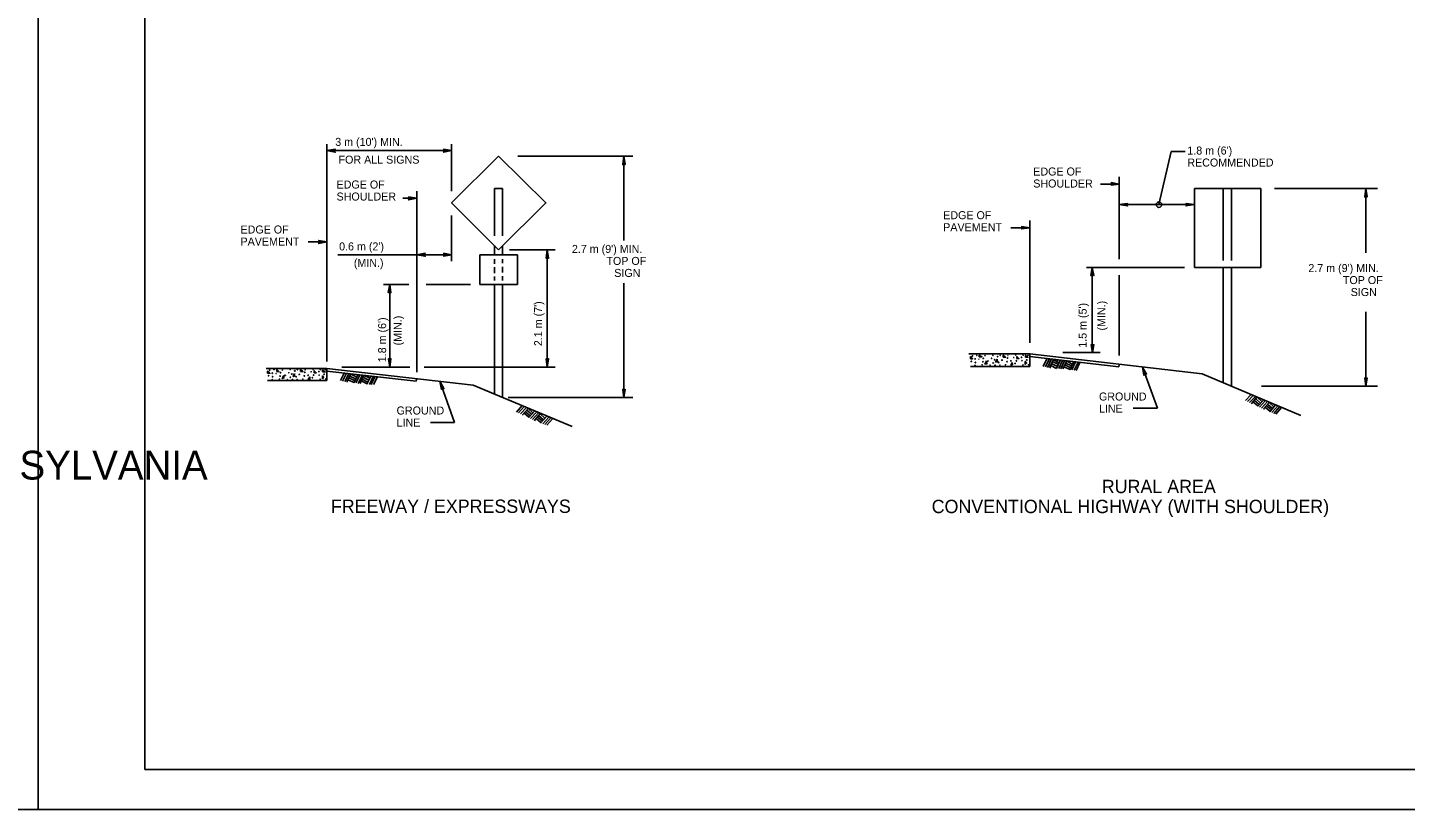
# Model space of a CAD drawing. Extents: x 644358 to 648627, y 294594 to 295782.
# Drawn here: x 646877 to 647394, y 294594 to 294887 of the extents above; entities that cross this region are included whole.
import ezdxf

# ---------------------------------------------------------------- set-up
doc = ezdxf.new("R2010")
doc.units = 0
for name, color, linetype in [('1', 7, 'Continuous'), ('2', 7, 'Continuous'), ('4', 7, 'Continuous'), ('PLT-BNDY', 7, 'Continuous')]:
    doc.layers.add(name, color=color, linetype=linetype)

msp = doc.modelspace()

# ---------------------------------------------------------------- linework, layer by layer
at = {"layer": '1'}
for p, q in [((646921.31, 295172.63), (646921.31, 294608.63)), ((647259.44, 294762.63), (647258.06, 294759.75)), ((647260.31, 294762.5), (647258.94, 294759.63)), ((647261.06, 294762.38), (647259.69, 294759.38)), ((647261.94, 294762.25), (647260.44, 294759.38)), ((647263.06, 294759), (647260.94, 294760.13)), ((647263.44, 294759.75), (647261.19, 294760.88)), ((647263.81, 294760.5), (647261.56, 294761.63)), ((647264.06, 294761.13), (647261.94, 294762.25)), ((647264.44, 294762), (647263.06, 294759)), ((647263.69, 294762), (647263.31, 294762.13)), ((647265.31, 294762), (647263.94, 294759)), ((647266.06, 294761.88), (647264.69, 294758.88)), ((647266.94, 294761.75), (647265.44, 294758.88)), ((647268.44, 294759.25), (647266.19, 294760.38)), ((647268.69, 294760), (647266.56, 294761)), ((647269.06, 294760.63), (647266.94, 294761.75)), ((647267.81, 294761.63), (647267.44, 294761.75)), ((647269.44, 294761.5), (647268.06, 294758.5)), ((647270.19, 294761.5), (647268.81, 294758.5)), ((647271.19, 294761.38), (647269.69, 294758.38)), ((647271.81, 294761.25), (647270.44, 294758.25)), ((646996.06, 294757.25), (646994.69, 294754.5)), ((646996.94, 294757.25), (646995.44, 294754.25)), ((646997.81, 294757), (646996.31, 294754.13)), ((646998.56, 294757), (646997.06, 294754)), ((646999.81, 294753.75), (646997.44, 294754.75)), ((646999.94, 294754.5), (646997.81, 294755.5)), ((647000.31, 294755.13), (646998.19, 294756.13)), ((647000.69, 294755.88), (646998.44, 294756.88)), ((647001.19, 294756.63), (646999.69, 294753.63)), ((647000.19, 294756.63), (646999.94, 294756.75)), ((647001.94, 294756.5), (647000.44, 294753.63)), ((647002.81, 294756.38), (647001.31, 294753.38)), ((647003.44, 294756.38), (647002.06, 294753.38)), ((647004.94, 294753.88), (647002.81, 294755)), ((647005.31, 294754.63), (647003.06, 294755.75)), ((647005.81, 294755.38), (647003.44, 294756.38)), ((647004.44, 294756.13), (647004.06, 294756.38)), ((647006.06, 294756.13), (647004.56, 294753.13)), ((647006.94, 294756), (647005.56, 294753)), ((647007.69, 294756), (647006.19, 294753)), ((647008.56, 294755.88), (647007.06, 294753)), ((647260.94, 294759.25), (647260.56, 294759.5)), ((647268.19, 294758.63), (647265.81, 294759.63)), ((647300.94, 294744.13), (647295.31, 294759.5)), ((646997.44, 294754), (646997.06, 294754.13)), ((647004.69, 294753.25), (647002.44, 294754.38)), ((647037.44, 294738.75), (647031.94, 294754.25)), ((647062.81, 294745.13), (647060.69, 294742.63)), ((647063.56, 294744.75), (647061.44, 294742.38)), ((647335.94, 294749.25), (647333.81, 294747)), ((647336.69, 294748.88), (647334.56, 294746.63)), ((647337.56, 294748.5), (647335.31, 294746.25)), ((647338.19, 294748.38), (647336.06, 294745.88)), ((647336.31, 294745.75), (647336.06, 294746)), ((647338.44, 294745), (647336.56, 294746.5)), ((647338.94, 294745.5), (647337.19, 294747)), ((647339.44, 294746), (647337.56, 294747.75)), ((647339.94, 294746.63), (647338.19, 294748.25)), ((647340.56, 294747.13), (647338.44, 294744.88)), ((647341.31, 294747), (647339.06, 294744.5)), ((647342.06, 294746.63), (647339.81, 294744.13)), ((647342.69, 294746.25), (647340.56, 294743.88)), ((647343.06, 294742.88), (647341.19, 294744.5)), ((647343.56, 294743.5), (647341.69, 294745)), ((647343.94, 294744), (647342.06, 294745.63)), ((647344.56, 294744.5), (647342.69, 294746.25)), ((647345.06, 294745.38), (647342.94, 294742.75)), ((647343.56, 294745.88), (647343.31, 294746)), ((647345.94, 294745), (647343.69, 294742.5)), ((647346.56, 294744.63), (647344.44, 294742.13)), ((647064.44, 294744.38), (647062.19, 294742)), ((647065.06, 294744), (647062.94, 294741.63)), ((647063.19, 294741.5), (647062.94, 294741.75)), ((647065.31, 294740.75), (647063.44, 294742.38)), ((647065.81, 294741.25), (647064.06, 294742.75)), ((647066.31, 294741.88), (647064.44, 294743.5)), ((647066.81, 294742.38), (647065.06, 294744)), ((647067.44, 294743), (647065.31, 294740.63)), ((647068.19, 294742.63), (647065.94, 294740.25)), ((647068.94, 294742.38), (647066.69, 294739.88)), ((647069.56, 294742.13), (647067.44, 294739.5)), ((647067.81, 294739.5), (647067.44, 294739.63)), ((647069.94, 294738.63), (647068.06, 294740.25)), ((647070.44, 294739.25), (647068.56, 294740.75)), ((647070.81, 294739.75), (647068.94, 294741.38)), ((647071.44, 294740.25), (647069.56, 294742)), ((647071.94, 294741), (647069.81, 294738.63)), ((647070.44, 294741.63), (647070.19, 294741.88)), ((647072.81, 294740.75), (647070.56, 294738.25)), ((647073.44, 294740.38), (647071.31, 294738)), ((647074.19, 294740.13), (647072.06, 294737.75)), ((647340.94, 294743.75), (647340.56, 294744)), ((647347.31, 294744.38), (647345.19, 294741.88)), ((647707.31, 294608.63), (646921.31, 294608.63)), ((646921.31, 294608.63), (647507.31, 294608.63))]:
    msp.add_line(p, q, dxfattribs=at)
for points in [[(647276.06, 294794), (647276.31, 294794.13), (647276.44, 294796.88), (647276.06, 294794), (647275.94, 294793.88), (647276.44, 294796.88), (647276.69, 294794.13), (647276.81, 294794), (647276.44, 294796.88), (647277.06, 294793.88), (647276.81, 294794)], [(647012.69, 294787.5), (647012.94, 294787.63), (647013.19, 294790.5), (647012.69, 294787.5), (647012.56, 294787.5), (647013.19, 294790.5), (647013.31, 294787.63), (647013.44, 294787.5), (647013.19, 294790.5), (647013.56, 294787.5), (647013.44, 294787.5)], [(647276.94, 294767.88), (647276.69, 294767.75), (647276.56, 294764.88), (647276.94, 294767.88), (647277.06, 294768), (647276.56, 294764.88), (647276.44, 294767.75), (647276.19, 294767.88), (647276.56, 294764.88), (647276.06, 294768), (647276.19, 294767.88)], [(647013.44, 294762.38), (647013.31, 294762.25), (647013.19, 294759.5), (647013.44, 294762.38), (647013.56, 294762.63), (647013.19, 294759.5), (647013.06, 294762.25), (647012.81, 294762.38), (647013.19, 294759.5), (647012.69, 294762.63), (647012.81, 294762.38)], [(647295.94, 294756.63), (647296.06, 294756.88), (647295.31, 294759.5), (647295.94, 294756.63), (647295.81, 294756.5), (647295.31, 294759.5), (647296.44, 294757), (647296.69, 294757), (647295.31, 294759.5), (647296.81, 294756.88), (647296.69, 294757)], [(647032.56, 294751.38), (647032.81, 294751.5), (647031.94, 294754.25), (647032.56, 294751.38), (647032.56, 294751.13), (647031.94, 294754.25), (647032.94, 294751.5), (647033.19, 294751.5), (647031.94, 294754.25), (647033.44, 294751.5), (647033.19, 294751.5)]]:
    msp.add_lwpolyline(points, dxfattribs=at)
for points in [[(647230.81, 294762.63), (647230.81, 294763.5), (647231.56, 294762.63)], [(647234.06, 294763.38), (647234.06, 294764), (647235.06, 294763.38)], [(647236.81, 294761.88), (647236.94, 294760.75), (647236.19, 294760.63)], [(647240.81, 294762.5), (647240.94, 294761.5), (647240.19, 294761.5)], [(647243.06, 294763.25), (647243.06, 294764), (647243.94, 294763.25)], [(647246.44, 294761.25), (647246.56, 294760.5), (647245.94, 294760.25)], [(647248.19, 294762.75), (647248.19, 294763.5), (647248.94, 294762.75)], [(647251.31, 294760.5), (647251.31, 294761.63), (647251.81, 294761)], [(647251.44, 294763.25), (647251.44, 294763.88), (647252.31, 294763.25)], [(646967.31, 294757.25), (646967.31, 294758), (646968.19, 294757.25)], [(646970.81, 294757.88), (646970.81, 294758.63), (646971.56, 294757.88)], [(646973.44, 294756.38), (646973.44, 294755.5), (646972.81, 294755.25)], [(646977.44, 294757.13), (646977.44, 294756.13), (646976.94, 294756)], [(646979.69, 294757.88), (646979.69, 294758.63), (646980.56, 294757.88)], [(646983.19, 294755.88), (646983.19, 294755), (646982.56, 294754.88)], [(646984.81, 294757.38), (646984.81, 294758.13), (646985.56, 294757.38)], [(646987.94, 294757.75), (646987.94, 294758.5), (646988.94, 294757.75)], [(646987.94, 294755.13), (646987.94, 294756.25), (646988.31, 294755.75)]]:
    msp.add_lwpolyline(points, close=True, dxfattribs=at)
for centre, radius in [((647301.43, 294820.46), 1.04), ((647231.1, 294761.66), 0.0979), ((647231.5, 294763.74), 0.0979), ((647232.51, 294762.61), 0.0979), ((647232.46, 294760.2), 0.056), ((647232.63, 294761.25), 0.0979), ((647233.15, 294763.92), 0.056), ((647233.98, 294762.5), 0.056), ((647235.18, 294760.39), 0.056), ((647235.43, 294761.52), 0.0979), ((647235.57, 294762.78), 0.0979), ((647236.25, 294763.83), 0.056), ((647237.32, 294761.8), 0.0979), ((647238.15, 294760.24), 0.056), ((647238.69, 294762.81), 0.056), ((647239.19, 294763.95), 0.056), ((647239.3, 294761.06), 0.0979), ((647239.83, 294762.28), 0.0979), ((647240.02, 294760.24), 0.0979), ((647240.94, 294763.49), 0.0979), ((647241.4, 294761.25), 0.0979), ((647241.83, 294760.27), 0.056), ((647241.93, 294763.92), 0.056), ((647242.6, 294762.14), 0.0979), ((647243.95, 294760.39), 0.056), ((647244.5, 294761.57), 0.0979), ((647244.69, 294762.93), 0.0979), ((647244.85, 294763.88), 0.056), ((647245.92, 294761.85), 0.0979), ((647247.06, 294763.13), 0.056), ((647247.52, 294760.91), 0.0979), ((647247.79, 294764), 0.056), ((647247.98, 294761.88), 0.0979), ((647249.96, 294763.19), 0.0979), ((647250.08, 294761.91), 0.056), ((647250.43, 294760.32), 0.056), ((647250.52, 294763.97), 0.056), ((647251.9, 294762.21), 0.0979), ((647252.36, 294763.94), 0.056), ((647252.55, 294760.44), 0.056), ((646967.71, 294756.29), 0.0979), ((646968.1, 294758.38), 0.0979), ((646969.11, 294757.25), 0.0979), ((646969.07, 294754.83), 0.056), ((646969.24, 294755.89), 0.0979), ((646969.76, 294758.55), 0.056), ((646970.59, 294757.13), 0.056), ((646971.79, 294755.03), 0.056), ((646972.04, 294756.15), 0.0979), ((646972.18, 294757.41), 0.0979), ((646972.86, 294758.46), 0.056), ((646973.93, 294756.44), 0.0979), ((646974.76, 294754.87), 0.056), ((646975.3, 294757.44), 0.056), ((646975.8, 294758.59), 0.056), ((646975.91, 294755.7), 0.0979), ((646976.43, 294756.92), 0.0979), ((646976.63, 294754.87), 0.0979), ((646977.55, 294758.13), 0.0979), ((646978.01, 294755.89), 0.0979), ((646978.44, 294754.91), 0.056), ((646978.53, 294758.55), 0.056), ((646979.21, 294756.77), 0.0979), ((646980.56, 294755.03), 0.056), ((646981.11, 294756.2), 0.0979), ((646981.3, 294757.56), 0.0979), ((646981.46, 294758.51), 0.056), ((646982.53, 294756.49), 0.0979), ((646983.67, 294757.77), 0.056), ((646984.13, 294755.55), 0.0979), ((646984.4, 294758.64), 0.056), ((646984.58, 294756.52), 0.0979), ((646986.57, 294757.83), 0.0979), ((646986.69, 294756.54), 0.056), ((646987.04, 294754.96), 0.056), ((646987.13, 294758.6), 0.056), ((646988.5, 294756.85), 0.0979), ((646988.97, 294758.57), 0.056), ((646989.16, 294755.08), 0.056)]:
    msp.add_circle(centre, radius, dxfattribs=at)
at = {"layer": '2'}
for p, q in [((647055.44, 294826.5), (647052.44, 294826.5)), ((647052.44, 294826.5), (647052.44, 294808.75)), ((647055.44, 294826.5), (647055.44, 294808.75)), ((647314.69, 294826.5), (647314.69, 294796.88)), ((647339.56, 294826.5), (647314.69, 294826.5)), ((647325.44, 294826.5), (647325.44, 294799.5)), ((647328.56, 294826.5), (647328.56, 294799.5)), ((647339.56, 294796.88), (647339.56, 294826.5)), ((647046.94, 294790.5), (647046.94, 294801.63)), ((647046.94, 294801.63), (647061.06, 294801.63)), ((647052.44, 294805.13), (647052.44, 294801.63)), ((647055.44, 294805), (647055.44, 294801.63)), ((647061.06, 294801.63), (647061.06, 294790.5)), ((647052.44, 294798.25), (647052.44, 294800)), ((647052.44, 294794.75), (647052.44, 294797)), ((647055.44, 294798.5), (647055.44, 294800)), ((647055.44, 294795), (647055.44, 294797.13)), ((647314.69, 294796.88), (647339.56, 294796.88)), ((647325.44, 294796.88), (647325.44, 294753.63)), ((647328.56, 294796.88), (647328.56, 294752.38)), ((647052.44, 294792), (647052.44, 294793.5)), ((647055.44, 294792), (647055.44, 294793.63)), ((647061.06, 294790.5), (647046.94, 294790.5)), ((647052.44, 294790.5), (647052.44, 294749.5)), ((647055.44, 294790.5), (647055.44, 294748.13)), ((647253.06, 294764.5), (647230.19, 294764.5)), ((647253.06, 294764.5), (647253.06, 294759.75)), ((647253.06, 294764.5), (647317.56, 294757)), ((647253.06, 294763.5), (647286.44, 294759.63)), ((647286.56, 294760.5), (647286.44, 294759.63)), ((646989.56, 294759), (646966.81, 294759)), ((646989.56, 294759), (646989.56, 294754.5)), ((646989.56, 294759), (647044.44, 294752.75)), ((646989.56, 294758), (647023.06, 294754.25)), ((647023.31, 294755.25), (647023.06, 294754.25)), ((647253.06, 294759.75), (647230.81, 294759.75)), ((647317.56, 294757), (647354.56, 294741.38)), ((646989.56, 294754.5), (646967.31, 294754.5)), ((647044.44, 294752.75), (647081.44, 294737.25))]:
    msp.add_line(p, q, dxfattribs=at)
msp.add_lwpolyline([(647053.94, 294803.5), (647071.69, 294821.13), (647053.94, 294838.63), (647036.31, 294821.13)], close=True, dxfattribs=at)
at = {"layer": '4'}
for p, q in [((646989.56, 294843.13), (646989.56, 294761.62)), ((647036.31, 294843.13), (647036.31, 294825.5)), ((647036.31, 294840.75), (646989.56, 294840.75)), ((647104.29, 294838.63), (647061.15, 294838.63)), ((647100.84, 294838.63), (647100.84, 294807)), ((647301.44, 294820.5), (647306.06, 294840.38)), ((647306.06, 294840.38), (647311.31, 294840.38)), ((647279.56, 294828.13), (647286.56, 294828.13)), ((647286.56, 294830.88), (647286.56, 294800)), ((647018.06, 294822.88), (647023.31, 294822.88)), ((647023.31, 294825.5), (647023.31, 294757.63)), ((647383.28, 294826.5), (647344.74, 294826.5)), ((647378.94, 294826.5), (647378.94, 294802.43)), ((647314.69, 294820.5), (647286.56, 294820.5)), ((647036.31, 294816.38), (647036.31, 294799.25)), ((647245.94, 294811.75), (647253.06, 294811.75)), ((647253.06, 294814.5), (647253.06, 294768.63)), ((646982.56, 294806.5), (646989.56, 294806.5)), ((647036.31, 294801.63), (646993.65, 294801.63)), ((647075.17, 294803.5), (647058.06, 294803.5)), ((647072.19, 294803.5), (647072.19, 294759.5)), ((647311.06, 294796.88), (647274.31, 294796.88)), ((647276.44, 294796.88), (647276.44, 294765)), ((647100.84, 294748.13), (647100.84, 294791)), ((647286.56, 294794), (647286.56, 294763.88)), ((647020.31, 294790.5), (647010.81, 294790.5)), ((647013.19, 294790.5), (647013.19, 294759.5)), ((647043.44, 294790.5), (647026.81, 294790.5)), ((647378.94, 294752.38), (647378.94, 294780.2)), ((647279.44, 294765), (647265.44, 294765)), ((647020.69, 294759.5), (646995.16, 294759.5)), ((647075.17, 294759.5), (647026.06, 294759.5)), ((647383.28, 294752.38), (647339.87, 294752.38)), ((647104.29, 294748.13), (647057.48, 294748.13)), ((647300.94, 294744.13), (647291.81, 294744.13)), ((647037.44, 294738.75), (647028.44, 294738.75))]:
    msp.add_line(p, q, dxfattribs=at)
for points in [[(646992.56, 294840.25), (646992.44, 294840.5), (646989.56, 294840.75), (646992.56, 294840.25), (646992.69, 294840.13), (646989.56, 294840.75), (646992.44, 294840.88), (646992.56, 294841.13), (646989.56, 294840.75), (646992.69, 294841.25), (646992.56, 294841.13)], [(647033.44, 294841.13), (647033.56, 294840.88), (647036.31, 294840.75), (647033.44, 294841.13), (647033.31, 294841.25), (647036.31, 294840.75), (647033.56, 294840.5), (647033.44, 294840.38), (647036.31, 294840.75), (647033.31, 294840.13), (647033.44, 294840.38)], [(647100.59, 294835.63), (647100.72, 294835.75), (647100.84, 294838.63), (647100.59, 294835.63), (647100.47, 294835.5), (647100.84, 294838.63), (647100.97, 294835.75), (647101.22, 294835.63), (647100.84, 294838.63), (647101.34, 294835.5), (647101.22, 294835.63)], [(647283.69, 294828.5), (647283.81, 294828.38), (647286.56, 294828.13), (647283.69, 294828.5), (647283.56, 294828.75), (647286.56, 294828.13), (647283.81, 294828), (647283.69, 294827.88), (647286.56, 294828.13), (647283.56, 294827.75), (647283.69, 294827.88)], [(647020.31, 294823.25), (647020.44, 294823), (647023.31, 294822.88), (647020.31, 294823.25), (647020.19, 294823.38), (647023.31, 294822.88), (647020.44, 294822.63), (647020.31, 294822.5), (647023.31, 294822.88), (647020.19, 294822.25), (647020.31, 294822.5)], [(647378.69, 294823.5), (647378.81, 294823.63), (647378.94, 294826.5), (647378.69, 294823.5), (647378.56, 294823.38), (647378.94, 294826.5), (647379.06, 294823.63), (647379.31, 294823.5), (647378.94, 294826.5), (647379.44, 294823.38), (647379.31, 294823.5)], [(647289.56, 294820.13), (647289.44, 294820.38), (647286.56, 294820.5), (647289.56, 294820.13), (647289.69, 294820), (647286.56, 294820.5), (647289.44, 294820.5), (647289.56, 294820.75), (647286.56, 294820.5), (647289.69, 294820.88), (647289.56, 294820.75)], [(647311.81, 294820.75), (647311.94, 294820.5), (647314.69, 294820.5), (647311.81, 294820.75), (647311.56, 294820.88), (647314.69, 294820.5), (647311.94, 294820.38), (647311.81, 294820.13), (647314.69, 294820.5), (647311.56, 294820), (647311.81, 294820.13)], [(647250.06, 294812.13), (647250.19, 294811.88), (647253.06, 294811.75), (647250.06, 294812.13), (647249.94, 294812.25), (647253.06, 294811.75), (647250.19, 294811.63), (647250.19, 294811.5), (647253.06, 294811.75), (647249.94, 294811.38), (647250.19, 294811.5)], [(646986.69, 294806.88), (646986.81, 294806.63), (646989.56, 294806.5), (646986.69, 294806.88), (646986.44, 294807), (646989.56, 294806.5), (646986.81, 294806.25), (646986.69, 294806.13), (646989.56, 294806.5), (646986.44, 294805.88), (646986.69, 294806.13)], [(647026.19, 294801.25), (647026.06, 294801.5), (647023.31, 294801.63), (647026.19, 294801.25), (647026.44, 294801.13), (647023.31, 294801.63), (647026.06, 294801.88), (647026.19, 294802), (647023.31, 294801.63), (647026.44, 294802.25), (647026.19, 294802)], [(647033.44, 294802.13), (647033.56, 294801.88), (647036.31, 294801.63), (647033.44, 294802.13), (647033.31, 294802.25), (647036.31, 294801.63), (647033.56, 294801.5), (647033.44, 294801.25), (647036.31, 294801.63), (647033.31, 294801.13), (647033.44, 294801.25)], [(647071.94, 294800.5), (647072.06, 294800.63), (647072.19, 294803.5), (647071.94, 294800.5), (647071.81, 294800.38), (647072.19, 294803.5), (647072.31, 294800.63), (647072.56, 294800.63), (647072.19, 294803.5), (647072.69, 294800.38), (647072.56, 294800.63)], [(647072.56, 294762.5), (647072.31, 294762.38), (647072.19, 294759.5), (647072.56, 294762.5), (647072.69, 294762.63), (647072.19, 294759.5), (647072.06, 294762.38), (647071.94, 294762.5), (647072.19, 294759.5), (647071.81, 294762.63), (647071.94, 294762.5)], [(647378.69, 294755.38), (647378.81, 294755.25), (647378.94, 294752.38), (647378.69, 294755.38), (647378.56, 294755.5), (647378.94, 294752.38), (647379.06, 294755.25), (647379.31, 294755.38), (647378.94, 294752.38), (647379.44, 294755.5), (647379.31, 294755.38)], [(647100.59, 294751.13), (647100.72, 294751), (647100.84, 294748.13), (647100.59, 294751.13), (647100.47, 294751.25), (647100.84, 294748.13), (647100.97, 294751), (647101.22, 294751.13), (647100.84, 294748.13), (647101.34, 294751.25), (647101.22, 294751.13)]]:
    msp.add_lwpolyline(points, dxfattribs=at)
at = {"layer": 'PLT-BNDY'}
for points in [[(646040.31, 295187.63), (646881.31, 295187.63), (646881.31, 294593.63), (646040.31, 294593.63)], [(646881.31, 295187.63), (647722.31, 295187.63), (647722.31, 294593.63), (646881.31, 294593.63)]]:
    msp.add_lwpolyline(points, close=True, dxfattribs=at)

# ---------------------------------------------------------------- texts
at = {"layer": '1'}
for s, height, p in [("1.8 m (6')", 3, (647312.06, 294839.25)), ('RECOMMENDED', 3, (647312.06, 294834.75)), ('EDGE OF', 3, (647254.31, 294831.38)), ('EDGE OF', 3, (646993.19, 294826.5)), ('SHOULDER', 3, (647254.31, 294826.88)), ('SHOULDER', 3, (646993.19, 294822)), ('EDGE OF', 3, (647220.56, 294815)), ('EDGE OF', 3, (646957.19, 294809.63)), ('PAVEMENT', 3, (647220.56, 294810.5)), ('PAVEMENT', 3, (646957.19, 294805.13)), ('GROUND', 3, (647278.94, 294747)), ('GROUND', 3, (647015.69, 294741.75)), ('LINE', 3, (647278.94, 294742.5)), ('LINE', 3, (647015.69, 294737.25)), ('COMMONWEALTH OF PENNSYLVANIA', 10.7828, (646678.9, 294717.36))]:
    msp.add_text(s, height=height, dxfattribs=at).set_placement(p)
for s, p in [("2.1 m (7')", (647070.25, 294767.39)), ("1.5 m (5')", (647274.32, 294766.78)), ('(MIN.)', (647281.35, 294773.25)), ("1.8 m (6')", (647011.78, 294761.35)), ('(MIN.)', (647017.62, 294767.66))]:
    msp.add_text(s, height=3, rotation=90, dxfattribs=at).set_placement(p)
at = {"layer": '2'}
for s, height, p in [("3 m (10') MIN.", 3, (646992.7, 294842.5)), ('FOR ALL SIGNS', 3, (646993.94, 294835.84)), ("0.6 m (2')", 3, (646994.15, 294803.29)), ("2.7 m (9') MIN.", 3, (647081.4, 294802.35)), ('(MIN.)', 3, (646999.67, 294797.13)), ('TOP OF', 3, (647094.34, 294797.85)), ('SIGN', 3, (647097.27, 294793.35)), ("2.7 m (9') MIN.", 3, (647357.42, 294795.17)), ('TOP OF', 3, (647370.36, 294790.67)), ('SIGN', 3, (647373.29, 294786.17)), ('RURAL AREA', 5, (647280, 294712.26)), ('FREEWAY / EXPRESSWAYS', 5, (646991.06, 294704.84)), ('CONVENTIONAL HIGHWAY (WITH SHOULDER)', 5, (647216.24, 294704.76))]:
    msp.add_text(s, height=height, dxfattribs=at).set_placement(p)

doc.saveas('drawing.dxf')
